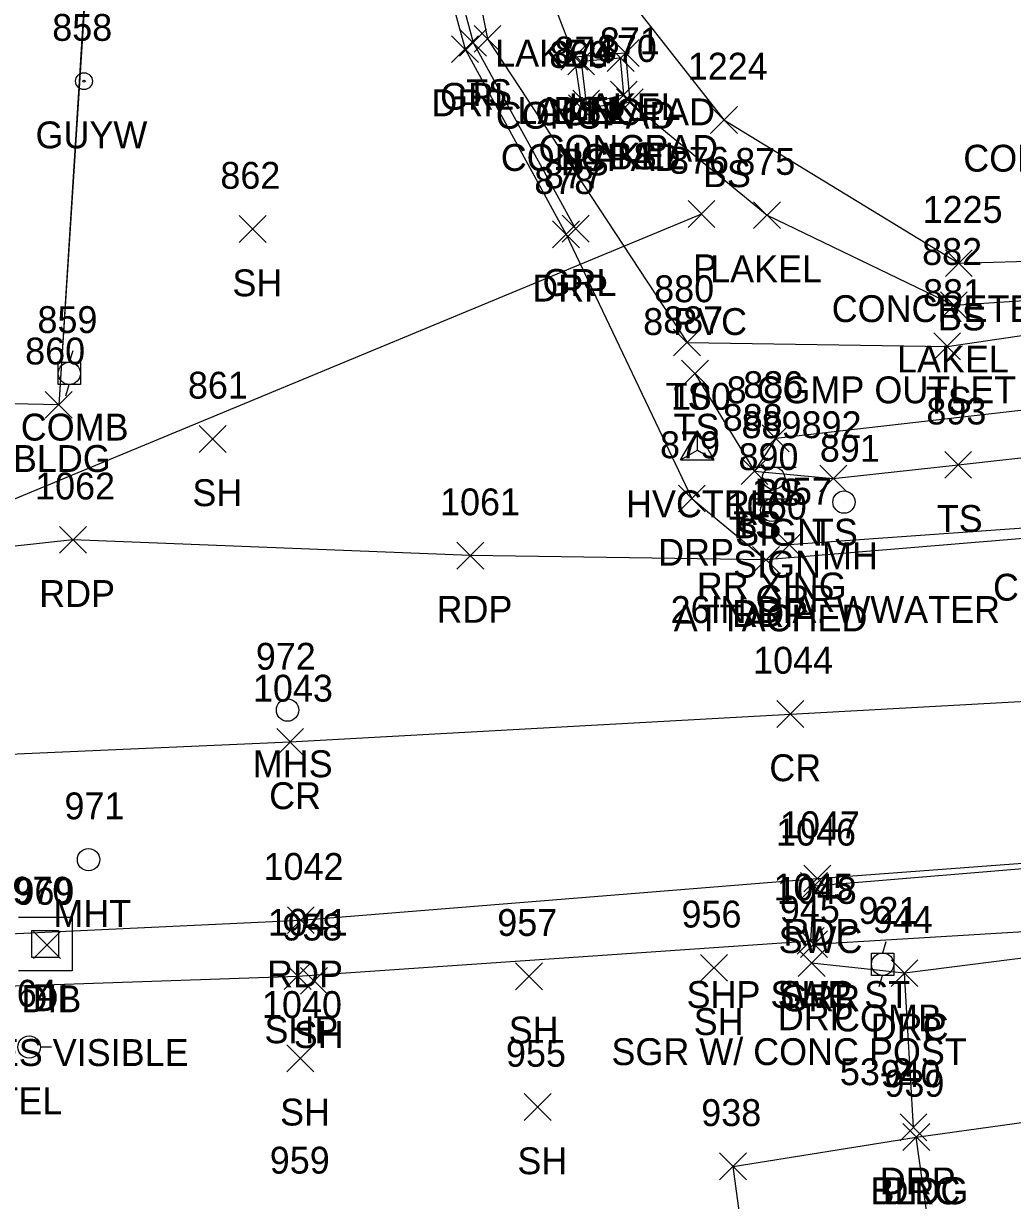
# Model space of a CAD drawing. Extents: x 1715662 to 1717487, y 887396 to 890004.
# Drawn here: x 1716781.4 to 1716855, y 888192.2 to 888279.7 of the extents above; entities that cross this region are included whole.
import ezdxf

# ---------------------------------------------------------------- set-up
doc = ezdxf.new("R2010")
doc.units = 0
for name, color, linetype in [('C_A', 7, 'Continuous'), ('C_I', 7, 'Continuous'), ('CPSM', 7, 'Continuous'), ('D_A', 7, 'Continuous'), ('D_C', 7, 'Continuous'), ('D_I', 7, 'Continuous'), ('D_TIC', 7, 'Continuous'), ('DCP', 7, 'Continuous'), ('DS', 7, 'Continuous'), ('L_A', 7, 'Continuous'), ('L_I', 7, 'Continuous'), ('L_TIC', 7, 'Continuous'), ('LAWE', 7, 'Continuous'), ('LBC', 7, 'Continuous'), ('LELB', 7, 'Continuous'), ('LS', 7, 'Continuous'), ('LSOGP', 7, 'Continuous'), ('P_A', 7, 'Continuous'), ('P_I', 7, 'Continuous'), ('P_TIC', 7, 'Continuous'), ('PET', 7, 'Continuous'), ('PRC', 7, 'Continuous'), ('PSP', 7, 'Continuous'), ('R_A', 7, 'Continuous'), ('R_C', 7, 'Continuous'), ('R_I', 7, 'Continuous'), ('R_TIC', 7, 'Continuous'), ('RDP', 7, 'Continuous'), ('RGR', 7, 'Continuous'), ('RSW', 7, 'Continuous'), ('S_A', 7, 'Continuous'), ('S_C', 7, 'Continuous'), ('S_I', 7, 'Continuous'), ('SSGN', 7, 'Continuous'), ('U_A', 7, 'Continuous'), ('U_C', 7, 'Continuous'), ('U_I', 7, 'Continuous'), ('UP', 7, 'Continuous'), ('UPGW', 7, 'Continuous'), ('USMH', 7, 'Continuous'), ('UTMH', 7, 'Continuous'), ('UUMH', 7, 'Continuous')]:
    doc.layers.add(name, color=color, linetype=linetype)

msp = doc.modelspace()

# ---------------------------------------------------------------- linework, layer by layer
at = {"layer": 'CPSM'}
for p, q in [((1716830.281, 888247.276), (1716831.531, 888249.441)), ((1716832.781, 888247.276), (1716831.531, 888249.441)), ((1716831.531, 888247.997), (1716831.531, 888249.441)), ((1716830.281, 888247.276), (1716831.531, 888247.997)), ((1716830.281, 888247.276), (1716832.781, 888247.276)), ((1716831.531, 888247.997), (1716831.531, 888247.997)), ((1716831.531, 888247.997), (1716832.781, 888247.276))]:
    msp.add_line(p, q, dxfattribs=at)
at = {"layer": 'D_TIC'}
for points in [[(1716830.837, 888264.562), (1716832.837, 888266.562)], [(1716832.837, 888264.562), (1716830.837, 888266.562)], [(1716782.125, 888210.163), (1716784.125, 888212.163)], [(1716784.125, 888210.163), (1716782.125, 888212.163)]]:
    msp.add_lwpolyline(points, dxfattribs=at)
at = {"layer": 'DCP'}
msp.add_lwpolyline([(1716831.837, 888265.562), (1716770.869, 888240.276)], dxfattribs=at)
at = {"layer": 'DS'}
for p, q in [((1716780.996, 888213.242), (1716784.996, 888213.242)), ((1716784.996, 888213.242), (1716784.996, 888209.242)), ((1716781.996, 888210.242), (1716781.996, 888212.242)), ((1716781.996, 888212.242), (1716783.996, 888212.242)), ((1716783.996, 888212.242), (1716783.996, 888210.242)), ((1716783.001, 888211.243), (1716783.001, 888211.243)), ((1716783.001, 888211.243), (1716783.001, 888211.243)), ((1716783.996, 888210.242), (1716781.996, 888210.242)), ((1716784.996, 888209.242), (1716780.996, 888209.242))]:
    msp.add_line(p, q, dxfattribs=at)
at = {"layer": 'L_TIC'}
for points in [[(1716814.908, 888277.599), (1716816.908, 888279.599)], [(1716816.908, 888277.599), (1716814.908, 888279.599)], [(1716821.371, 888276.267), (1716823.371, 888278.267)], [(1716823.371, 888276.267), (1716821.371, 888278.267)], [(1716821.371, 888276.267), (1716823.371, 888278.267)], [(1716823.371, 888276.267), (1716821.371, 888278.267)], [(1716821.882, 888275.912), (1716823.882, 888277.912)], [(1716823.882, 888275.912), (1716821.882, 888277.912)], [(1716824.821, 888276.17), (1716826.821, 888278.17)], [(1716826.821, 888276.17), (1716824.821, 888278.17)], [(1716825.189, 888276.556), (1716827.189, 888278.556)], [(1716827.189, 888276.556), (1716825.189, 888278.556)], [(1716825.062, 888273.45), (1716827.062, 888275.45)], [(1716827.062, 888273.45), (1716825.062, 888275.45)], [(1716821.932, 888272.438), (1716823.932, 888274.438)], [(1716823.932, 888272.438), (1716821.932, 888274.438)], [(1716822.255, 888272.772), (1716824.255, 888274.772)], [(1716824.255, 888272.772), (1716822.255, 888274.772)], [(1716825.504, 888272.884), (1716827.504, 888274.884)], [(1716827.504, 888272.884), (1716825.504, 888274.884)], [(1716825.504, 888272.884), (1716827.504, 888274.884)], [(1716827.504, 888272.884), (1716825.504, 888274.884)], [(1716832.507, 888271.565), (1716834.507, 888273.565)], [(1716834.507, 888271.565), (1716832.507, 888273.565)], [(1716835.716, 888264.482), (1716837.716, 888266.482)], [(1716837.716, 888264.482), (1716835.716, 888266.482)], [(1716797.441, 888263.444), (1716799.441, 888265.444)], [(1716799.441, 888263.444), (1716797.441, 888265.444)], [(1716849.988, 888260.906), (1716851.988, 888262.906)], [(1716851.988, 888260.906), (1716849.988, 888262.906)], [(1716849.622, 888257.774), (1716851.622, 888259.774)], [(1716851.622, 888257.774), (1716849.622, 888259.774)], [(1716829.764, 888255.002), (1716831.764, 888257.002)], [(1716831.764, 888255.002), (1716829.764, 888257.002)], [(1716849.124, 888254.716), (1716851.124, 888256.716)], [(1716851.124, 888254.716), (1716849.124, 888256.716)], [(1716830.352, 888252.697), (1716832.352, 888254.697)], [(1716832.352, 888252.697), (1716830.352, 888254.697)], [(1716783.001, 888250.37), (1716785.001, 888252.37)], [(1716785.001, 888250.37), (1716783.001, 888252.37)], [(1716836.365, 888247.868), (1716838.365, 888249.868)], [(1716838.365, 888247.868), (1716836.365, 888249.868)], [(1716794.46, 888247.826), (1716796.46, 888249.826)], [(1716796.46, 888247.826), (1716794.46, 888249.826)], [(1716834.782, 888245.432), (1716836.782, 888247.432)], [(1716836.782, 888245.432), (1716834.782, 888247.432)], [(1716834.782, 888245.432), (1716836.782, 888247.432)], [(1716836.782, 888245.432), (1716834.782, 888247.432)], [(1716849.938, 888245.905), (1716851.938, 888247.905)], [(1716851.938, 888245.905), (1716849.938, 888247.905)], [(1716840.647, 888244.886), (1716842.647, 888246.886)], [(1716842.647, 888244.886), (1716840.647, 888246.886)], [(1716831.77, 888208.468), (1716833.77, 888210.468)], [(1716833.77, 888208.468), (1716831.77, 888210.468)], [(1716818.002, 888207.843), (1716820.002, 888209.843)], [(1716820.002, 888207.843), (1716818.002, 888209.843)], [(1716802.006, 888207.503), (1716804.006, 888209.503)], [(1716804.006, 888207.503), (1716802.006, 888209.503)], [(1716800.989, 888201.734), (1716802.989, 888203.734)], [(1716802.989, 888201.734), (1716800.989, 888203.734)], [(1716818.65, 888198.11), (1716820.65, 888200.11)], [(1716820.65, 888198.11), (1716818.65, 888200.11)], [(1716846.826, 888195.875), (1716848.826, 888197.875)], [(1716848.826, 888195.875), (1716846.826, 888197.875)]]:
    msp.add_lwpolyline(points, dxfattribs=at)
at = {"layer": 'LAWE'}
msp.add_lwpolyline([(1716792.923, 888333.593), (1716808.09, 888324.58), (1716820.08, 888290.735), (1716820.719, 888281.539), (1716822.371, 888277.267), (1716826.189, 888277.556), (1716826.504, 888273.884), (1716836.716, 888265.482), (1716850.622, 888258.774), (1716877.174, 888260.555), (1716881.322, 888255.897), (1716887.736, 888253.856), (1716892.995, 888253.305), (1716893.169, 888249.274), (1716879.794, 888244.823)], dxfattribs=at)
at = {"layer": 'LBC'}
for points in [[(1716790.149, 888346.756), (1716790.149, 888340.324), (1716789.905, 888340.162), (1716789.239, 888334.166), (1716788.401, 888319.776), (1716786.544, 888291.649), (1716784.001, 888251.37), (1716721.337, 888252.742), (1716722.055, 888265.932)], [(1716884.889, 888132.553), (1716884.371, 888132.666), (1716857.375, 888128.726), (1716852.404, 888164.292), (1716847.826, 888196.875), (1716876.377, 888200.838), (1716883.534, 888201.862), (1716883.701, 888201.987), (1716884.835, 888201.978)]]:
    msp.add_lwpolyline(points, dxfattribs=at)
at = {"layer": 'LELB'}
for points in [[(1716798.784, 888338.684), (1716807.198, 888328.202), (1716816.689, 888310.638), (1716822.622, 888293.629), (1716826.404, 888294.991), (1716827.92, 888291.14), (1716823.715, 888289.67), (1716822.512, 888293.041), (1716821.152, 888288.315), (1716833.507, 888272.565), (1716850.988, 888261.906), (1716864.723, 888262.295), (1716881.119, 888261.054)], [(1716791.288, 888331.615), (1716796.122, 888325.707), (1716805.751, 888321.457), (1716813.357, 888291.514), (1716815.908, 888278.599), (1716830.764, 888256.002), (1716850.124, 888255.716), (1716867.758, 888258.309)], [(1716822.371, 888277.267), (1716822.932, 888273.438), (1716826.504, 888273.884)], [(1716831.352, 888253.697), (1716835.782, 888246.432), (1716841.647, 888245.886), (1716850.938, 888246.905), (1716869.789, 888249.001), (1716870.22, 888257.561), (1716875.534, 888257.948), (1716880.311, 888254.139), (1716887.482, 888251.965), (1716891.986, 888252.334), (1716891.594, 888250.562), (1716886.869, 888248.35), (1716879.09, 888248.225)], [(1716867.758, 888258.309), (1716868.17, 888252.377), (1716837.365, 888248.868), (1716835.782, 888246.432)]]:
    msp.add_lwpolyline(points, dxfattribs=at)
at = {"layer": 'LS'}
for points in [[(1716826.062, 888274.45), (1716825.821, 888277.17), (1716822.882, 888276.912), (1716823.255, 888273.772)], [(1716823.255, 888273.772), (1716826.062, 888274.45)]]:
    msp.add_lwpolyline(points, dxfattribs=at)
at = {"layer": 'LSOGP'}
msp.add_lwpolyline([(1717115.574, 888330.215), (1717057.48, 888334.024), (1717034.288, 888346.634), (1716994.901, 888331.052), (1716971.92, 888329.412), (1716927.78, 888315.882), (1716905.332, 888322.14), (1716871.243, 888333.888), (1716808.968, 888341.314), (1716791.424, 888346.366), (1716790.32, 888340.433), (1716790.148, 888340.324), (1716789.905, 888340.162), (1716789.239, 888334.166), (1716791.288, 888331.615), (1716789.775, 888320.755), (1716788.406, 888319.776), (1716784.007, 888251.37), (1716721.333, 888252.74), (1716722.056, 888265.932), (1716706.46, 888265.745)], dxfattribs=at)
at = {"layer": 'P_TIC'}
for points in [[(1716784.061, 888240.323), (1716786.061, 888242.323)], [(1716786.061, 888240.323), (1716784.061, 888242.323)], [(1716813.633, 888239.145), (1716815.633, 888241.145)], [(1716815.633, 888239.145), (1716813.633, 888241.145)], [(1716835.634, 888238.831), (1716837.634, 888240.831)], [(1716837.634, 888238.831), (1716835.634, 888240.831)], [(1716837.45, 888227.358), (1716839.45, 888229.358)], [(1716839.45, 888227.358), (1716837.45, 888229.358)], [(1716800.229, 888225.279), (1716802.229, 888227.279)], [(1716802.229, 888225.279), (1716800.229, 888227.279)], [(1716839.455, 888215.113), (1716841.455, 888217.113)], [(1716841.455, 888215.113), (1716839.455, 888217.113)], [(1716801.021, 888212.013), (1716803.021, 888214.013)], [(1716803.021, 888212.013), (1716801.021, 888214.013)], [(1716838.964, 888210.481), (1716840.964, 888212.481)], [(1716840.964, 888210.481), (1716838.964, 888212.481)], [(1716800.777, 888207.857), (1716802.777, 888209.857)], [(1716802.777, 888207.857), (1716800.777, 888209.857)]]:
    msp.add_lwpolyline(points, dxfattribs=at)
at = {"layer": 'PET'}
msp.add_lwpolyline([(1716669.133, 888208.315), (1716709.505, 888208.714), (1716740.373, 888211.068), (1716775.556, 888211.777), (1716802.021, 888213.013), (1716840.455, 888216.113), (1716878.657, 888218.974), (1716877.597, 888230.504), (1716876.883, 888242.851), (1716857.915, 888241.594), (1716836.634, 888239.831), (1716814.633, 888240.145), (1716785.061, 888241.323), (1716771.928, 888239.872), (1716746.815, 888241.658), (1716719.438, 888242.78), (1716699.752, 888242.907), (1716680.829, 888242.531), (1716671.322, 888244.592)], dxfattribs=at)
at = {"layer": 'PRC'}
msp.add_lwpolyline([(1716669.076, 888220.596), (1716706.499, 888221.389), (1716739.728, 888221.602), (1716772.982, 888225.054), (1716801.229, 888226.279), (1716838.45, 888228.358), (1716877.597, 888230.504)], dxfattribs=at)
at = {"layer": 'PSP'}
msp.add_lwpolyline([(1716669.372, 888204.532), (1716709.372, 888205.407), (1716740.477, 888206.521), (1716776.451, 888207.971), (1716801.777, 888208.857), (1716839.964, 888211.481)], dxfattribs=at)
at = {"layer": 'R_TIC'}
for points in [[(1716813.245, 888276.838), (1716815.245, 888278.838)], [(1716815.245, 888276.838), (1716813.245, 888278.838)], [(1716813.838, 888277.323), (1716815.838, 888279.323)], [(1716815.838, 888277.323), (1716813.838, 888279.323)], [(1716820.755, 888263.054), (1716822.755, 888265.054)], [(1716822.755, 888263.054), (1716820.755, 888265.054)], [(1716821.467, 888263.473), (1716823.467, 888265.473)], [(1716823.467, 888263.473), (1716821.467, 888265.473)], [(1716830.123, 888243.394), (1716832.123, 888245.394)], [(1716832.123, 888243.394), (1716830.123, 888245.394)], [(1716837.37, 888239.943), (1716839.37, 888241.943)], [(1716839.37, 888239.943), (1716837.37, 888241.943)], [(1716835.634, 888238.831), (1716837.634, 888240.831)], [(1716837.634, 888238.831), (1716835.634, 888240.831)], [(1716839.214, 888214.564), (1716841.214, 888216.564)], [(1716841.214, 888214.564), (1716839.214, 888216.564)], [(1716838.964, 888210.481), (1716840.964, 888212.481)], [(1716840.964, 888210.481), (1716838.964, 888212.481)], [(1716839.215, 888210.23), (1716841.215, 888212.23)], [(1716841.215, 888210.23), (1716839.215, 888212.23)], [(1716839.032, 888208.825), (1716841.032, 888210.825)], [(1716841.032, 888208.825), (1716839.032, 888210.825)], [(1716845.948, 888208.068), (1716847.948, 888210.068)], [(1716847.948, 888208.068), (1716845.948, 888210.068)], [(1716845.948, 888208.068), (1716847.948, 888210.068)], [(1716847.948, 888208.068), (1716845.948, 888210.068)], [(1716846.619, 888196.606), (1716848.619, 888198.606)], [(1716848.619, 888196.606), (1716846.619, 888198.606)], [(1716846.826, 888195.875), (1716848.826, 888197.875)], [(1716848.826, 888195.875), (1716846.826, 888197.875)], [(1716833.184, 888193.695), (1716835.184, 888195.695)], [(1716835.184, 888193.695), (1716833.184, 888195.695)]]:
    msp.add_lwpolyline(points, dxfattribs=at)
at = {"layer": 'RDP'}
for points in [[(1716788.401, 888319.776), (1716804.113, 888319.602), (1716810.581, 888291.273), (1716814.245, 888277.838), (1716821.755, 888264.054), (1716831.123, 888244.394), (1716836.634, 888239.831)], [(1716876.377, 888200.838), (1716875.716, 888209.526), (1716867.474, 888211.687), (1716846.948, 888209.068)], [(1716847.619, 888197.606), (1716846.948, 888209.068), (1716840.032, 888209.825)], [(1716857.375, 888128.726), (1716843.611, 888126.909), (1716838.26, 888164.679), (1716834.184, 888194.695), (1716847.826, 888196.875)]]:
    msp.add_lwpolyline(points, dxfattribs=at)
at = {"layer": 'RGR'}
for points in [[(1716789.776, 888320.755), (1716804.987, 888320.51), (1716811.337, 888291.322), (1716814.838, 888278.323), (1716822.467, 888264.473)], [(1716877.112, 888243.702), (1716838.37, 888240.943)], [(1716840.215, 888211.23), (1716878.419, 888213.528)]]:
    msp.add_lwpolyline(points, dxfattribs=at)
at = {"layer": 'RSW'}
msp.add_lwpolyline([(1716839.964, 888211.481), (1716840.214, 888215.564), (1716878.468, 888218.75), (1716878.816, 888213.646)], dxfattribs=at)
at = {"layer": 'SSGN'}
for p, q in [((1716835.56, 888246.736), (1716838.893, 888246.736)), ((1716837.206, 888245.903), (1716837.206, 888245.903)), ((1716835.414, 888244.361), (1716838.747, 888244.361)), ((1716837.061, 888243.527), (1716837.061, 888243.527))]:
    msp.add_line(p, q, dxfattribs=at)
for centre in [(1716837.206, 888245.903), (1716837.061, 888243.527)]:
    msp.add_circle(centre, 0.833, dxfattribs=at)
at = {"layer": 'UP'}
for p, q in [((1716785.04, 888255.374), (1716784.79, 888254.541)), ((1716783.957, 888252.874), (1716783.957, 888254.541)), ((1716783.957, 888254.541), (1716785.624, 888254.541)), ((1716785.624, 888254.541), (1716785.624, 888252.874)), ((1716784.79, 888253.708), (1716784.79, 888253.708)), ((1716785.624, 888252.874), (1716783.957, 888252.874)), ((1716784.54, 888252.041), (1716784.79, 888252.874)), ((1716845.569, 888211.403), (1716845.319, 888210.57)), ((1716844.485, 888208.903), (1716844.485, 888210.57)), ((1716844.485, 888210.57), (1716846.152, 888210.57)), ((1716846.152, 888210.57), (1716846.152, 888208.903)), ((1716845.319, 888209.737), (1716845.319, 888209.737)), ((1716846.152, 888208.903), (1716844.485, 888208.903)), ((1716845.069, 888208.07), (1716845.319, 888208.903)), ((1716781.801, 888203.577), (1716781.801, 888203.577)), ((1716783.468, 888203.577), (1716782.635, 888203.577)), ((1716782.635, 888203.577), (1716782.635, 888203.577)), ((1716783.468, 888203.577), (1716783.468, 888203.577))]:
    msp.add_line(p, q, dxfattribs=at)
for centre in [(1716784.79, 888253.708), (1716845.319, 888209.737), (1716781.801, 888203.577)]:
    msp.add_circle(centre, 0.833, dxfattribs=at)
at = {"layer": 'UPGW'}
for radius in [0.625, 0.0833]:
    msp.add_circle((1716785.881, 888275.453), radius, dxfattribs=at)
at = {"layer": 'USMH'}
for p, q in [((1716801.031, 888228.653), (1716801.031, 888228.653)), ((1716801.864, 888228.653), (1716801.864, 888228.653))]:
    msp.add_line(p, q, dxfattribs=at)
msp.add_circle((1716801.031, 888228.653), 0.833, dxfattribs=at)
at = {"layer": 'UTMH'}
for p, q in [((1716786.222, 888217.519), (1716786.222, 888217.519)), ((1716787.056, 888217.519), (1716787.056, 888217.519))]:
    msp.add_line(p, q, dxfattribs=at)
msp.add_circle((1716786.222, 888217.519), 0.833, dxfattribs=at)
at = {"layer": 'UUMH'}
for p, q in [((1716842.442, 888244.13), (1716842.442, 888244.13)), ((1716843.275, 888244.13), (1716843.275, 888244.13))]:
    msp.add_line(p, q, dxfattribs=at)
msp.add_circle((1716842.442, 888244.13), 0.833, dxfattribs=at)

# ---------------------------------------------------------------- texts
at = {"layer": 'C_A'}
msp.add_text('HVCTRL', height=2, dxfattribs=at).set_placement((1716826.224, 888242.997))
at = {"layer": 'C_I'}
msp.add_text('100', height=2, dxfattribs=at).set_placement((1716829.571, 888250.997))
at = {"layer": 'D_A'}
for s, p in [('P', (1716831.215, 888260.562)), ('DIB', (1716781.227, 888206.163)), ('DI', (1716782.056, 888206.243))]:
    msp.add_text(s, height=2, dxfattribs=at).set_placement(p)
at = {"layer": 'D_C'}
for s, p in [('8 PVC', (1716827.498, 888256.562)), ('8 CGMP OUTLET ORIGIN UNKNOWN', (1716833.708, 888251.48)), ('NO PIPES VISIBLE', (1716770.18, 888202.163))]:
    msp.add_text(s, height=2, dxfattribs=at).set_placement(p)
at = {"layer": 'D_I'}
for s, p in [('876', (1716829.42, 888268.562)), ('970', (1716780.552, 888214.243)), ('969', (1716780.708, 888214.163))]:
    msp.add_text(s, height=2, dxfattribs=at).set_placement(p)
at = {"layer": 'L_A'}
for s, p in [('LAKEL', (1716816.483, 888276.539)), ('TS', (1716814.318, 888273.599)), ('LAKEL', (1716821.953, 888272.556)), ('CONCPAD', (1716816.528, 888271.912)), ('LAKEL', (1716818.135, 888272.267)), ('CONCPAD', (1716819.467, 888272.17)), ('BS', (1716820.812, 888272.267)), ('CONCPAD', (1716819.708, 888269.45)), ('LAKEL', (1716822.267, 888268.884)), ('BS', (1716824.944, 888268.884)), ('CONCPAD', (1716816.901, 888268.772)), ('BS', (1716821.373, 888268.438)), ('BS', (1716831.948, 888267.565)), ('LAKEL', (1716832.479, 888260.482)), ('SH', (1716796.929, 888259.444)), ('BS', (1716849.429, 888256.906)), ('LAKEL', (1716846.386, 888253.774)), ('TS', (1716829.173, 888251.002)), ('TS', (1716848.533, 888250.716)), ('TS', (1716829.761, 888248.697)), ('BLDG', (1716780.592, 888246.37)), ('SH', (1716793.948, 888243.826)), ('BS', (1716835.805, 888243.868)), ('TS', (1716849.347, 888241.905)), ('TS', (1716834.192, 888241.432)), ('BS', (1716834.223, 888241.432)), ('TS', (1716840.056, 888240.886)), ('SH', (1716831.258, 888204.468)), ('SH', (1716801.494, 888203.503)), ('SH', (1716817.49, 888203.843)), ('SH', (1716800.477, 888197.734)), ('SH', (1716818.138, 888194.11)), ('BLDG', (1716844.417, 888191.875))]:
    msp.add_text(s, height=2, dxfattribs=at).set_placement(p)
at = {"layer": 'L_I'}
for s, p in [('874', (1716820.893, 888276.772)), ('870', (1716824.055, 888276.884)), ('870', (1716824.055, 888276.884)), ('871', (1716824.267, 888277.45)), ('869', (1716820.514, 888276.438)), ('1224', (1716830.814, 888275.565)), ('875', (1716834.353, 888268.482)), ('862', (1716796.032, 888267.444)), ('1225', (1716848.295, 888264.906)), ('882', (1716848.26, 888261.774)), ('880', (1716828.315, 888259.002)), ('881', (1716848.329, 888258.716)), ('887', (1716828.99, 888256.697)), ('860', (1716781.505, 888254.37)), ('861', (1716793.617, 888251.826)), ('886', (1716834.947, 888251.868)), ('893', (1716848.576, 888249.905)), ('888', (1716833.42, 888249.432)), ('888', (1716833.42, 888249.432)), ('892', (1716839.285, 888248.886)), ('956', (1716830.352, 888212.468)), ('958', (1716800.644, 888211.503)), ('957', (1716816.64, 888211.843)), ('1040', (1716799.131, 888205.734)), ('955', (1716817.288, 888202.11)), ('939', (1716845.456, 888199.875)), ('959', (1716799.709, 888194.155))]:
    msp.add_text(s, height=2, dxfattribs=at).set_placement(p)
at = {"layer": 'P_A'}
for s, p in [('RDP', (1716782.549, 888236.323)), ('RDP', (1716812.121, 888235.145)), ('RDP', (1716834.122, 888234.831)), ('CR', (1716836.883, 888223.358)), ('CR', (1716799.662, 888221.279)), ('RDP', (1716837.943, 888211.113)), ('RDP', (1716799.509, 888208.013)), ('SHP', (1716837.499, 888206.481)), ('SHP', (1716799.313, 888203.857))]:
    msp.add_text(s, height=2, dxfattribs=at).set_placement(p)
at = {"layer": 'P_I'}
for s, p in [('1062', (1716782.242, 888244.323)), ('1061', (1716812.381, 888243.145)), ('1060', (1716833.728, 888242.831)), ('1044', (1716835.678, 888231.358)), ('1043', (1716798.457, 888229.279)), ('1047', (1716837.683, 888219.113)), ('1042', (1716799.249, 888216.013)), ('1045', (1716837.192, 888214.481)), ('1041', (1716799.572, 888211.857))]:
    msp.add_text(s, height=2, dxfattribs=at).set_placement(p)
at = {"layer": 'R_A'}
for s, p in [('GRL', (1716812.382, 888273.323)), ('DRP', (1716811.733, 888272.838)), ('GRL', (1716820.011, 888259.473)), ('DRP', (1716819.243, 888259.054)), ('DRP', (1716828.611, 888239.394)), ('CURBC', (1716853.534, 888236.793)), ('GRR', (1716835.859, 888235.943)), ('DRP', (1716834.122, 888234.831)), ('SWC', (1716837.576, 888210.564)), ('SHP SWC ST', (1716830.727, 888206.481)), ('GRR', (1716837.703, 888206.23)), ('DRP', (1716837.52, 888204.825)), ('DRC', (1716844.436, 888204.068)), ('DRP', (1716844.436, 888204.068)), ('DRP', (1716845.107, 888192.606)), ('DRC', (1716845.314, 888191.875))]:
    msp.add_text(s, height=2, dxfattribs=at).set_placement(p)
at = {"layer": 'R_C'}
for s, p in [('CONCRETE 2.5 X 2', (1716851.32, 888268.72)), ('CONCRETE TIE TO LAST WITH RXR', (1716841.527, 888257.523)), ('SGR W/ CONC POST', (1716825.136, 888202.23))]:
    msp.add_text(s, height=2, dxfattribs=at).set_placement(p)
at = {"layer": 'R_I'}
for s, p in [('877', (1716820.105, 888267.473)), ('878', (1716819.393, 888267.054)), ('879', (1716828.753, 888247.394)), ('1057', (1716835.599, 888243.943)), ('1060', (1716833.728, 888242.831)), ('1046', (1716837.387, 888218.564)), ('1045', (1716837.192, 888214.481)), ('1048', (1716837.443, 888214.23)), ('945', (1716837.67, 888212.825)), ('944', (1716844.586, 888212.068)), ('944', (1716844.586, 888212.068)), ('940', (1716845.17, 888200.606)), ('939', (1716845.456, 888199.875)), ('938', (1716831.822, 888197.695))]:
    msp.add_text(s, height=2, dxfattribs=at).set_placement(p)
at = {"layer": 'S_A'}
for p in [(1716834.344, 888240.883), (1716834.198, 888238.507)]:
    msp.add_text('SIGN', height=2, dxfattribs=at).set_placement(p)
at = {"layer": 'S_C'}
for s, p in [('RR XING', (1716831.494, 888236.883)), ('ATTACHED', (1716829.773, 888234.507))]:
    msp.add_text(s, height=2, dxfattribs=at).set_placement(p)
at = {"layer": 'S_I'}
for s, p in [('889', (1716834.817, 888248.883)), ('890', (1716834.592, 888246.507))]:
    msp.add_text(s, height=2, dxfattribs=at).set_placement(p)
at = {"layer": 'U_A'}
for s, p in [('GUYW', (1716782.275, 888270.453)), ('COMB', (1716781.176, 888248.708)), ('MH', (1716840.804, 888239.13)), ('MHS', (1716798.448, 888223.653)), ('MHT', (1716783.6, 888212.519)), ('COMB', (1716841.704, 888204.737)), ('TEL', (1716779.361, 888198.577))]:
    msp.add_text(s, height=2, dxfattribs=at).set_placement(p)
at = {"layer": 'U_C'}
for s, p in [('26IN DIA. WWATER', (1716829.537, 888235.13)), ('53-2', (1716842.137, 888200.737))]:
    msp.add_text(s, height=2, dxfattribs=at).set_placement(p)
at = {"layer": 'U_I'}
for s, p in [('858', (1716783.519, 888278.453)), ('859', (1716782.42, 888256.708)), ('891', (1716840.647, 888247.13)), ('972', (1716798.669, 888231.653)), ('971', (1716784.427, 888220.519)), ('921', (1716843.523, 888212.737)), ('964', (1716779.392, 888206.577))]:
    msp.add_text(s, height=2, dxfattribs=at).set_placement(p)

doc.saveas('drawing.dxf')
